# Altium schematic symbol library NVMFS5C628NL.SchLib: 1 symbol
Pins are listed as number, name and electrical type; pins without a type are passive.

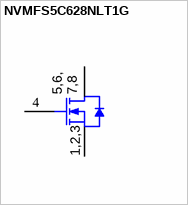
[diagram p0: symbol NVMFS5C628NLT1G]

## NVMFS5C628NLT1G
designator Q?
MOSFET N-CH 60V SO8FL; Manufacturer: Used in BOM report; SymbolVersion: use current date i.e. 2008-05-20; SymbolCreator: Use a-id; CompType: Used in some BOM reports.  Useful for finding later.; U/M: EA, IN, or GM; Rds On Max: 2.4mR; Input Capacitance: 3.6nF; Max Power Dissipation: 3.7W
footprint PG-TDSON-8 (Infineon recommended land pattern)
pins: 1 S, 2 S, 3 S, 4 G, 5 D, 6 D, 7 D, 8 D, 9 D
